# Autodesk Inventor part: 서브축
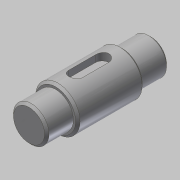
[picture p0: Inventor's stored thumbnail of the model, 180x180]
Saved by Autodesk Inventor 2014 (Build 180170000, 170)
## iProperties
Created: 2019-03
Part Number: 서브축
Material: 강철, 연강
Document SubType Name: Modeling
Designer: mduedu
Density: 1 g/cm^3
Appearance: 강철
Author: mduedu
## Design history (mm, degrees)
sketch "스케치1"
  geometry: L1 (0, 0)-(12, 0); L2 (12, 0)-(12, 8); L3 (12, 8)-(0, 8); L4 (0, 8)-(0, 0); L5 (12, 0)-(42, 0); L6 (42, 0)-(42, 10); L7 (42, 10)-(12, 10); L8 (12, 10)-(12, 0); L9 (42, 0)-(55, 0); L10 (55, 0)-(55, 8); L11 (55, 8)-(42, 8); L12 (42, 8)-(42, 0)
  constraints: 24 end point, 6 parallel, 3 horizontal, 3 perpendicular
  dimensions: "d0" = 16 diameter of L3 L1; "d2" = 20 diameter of L7 L5; "d3" = 16 diameter of L11 L9; "d4" = 12 distance of L2.end L3.end; "d5" = 30 distance of L6.end L7.end; "d6" = 55 distance between parallel lines of L10 L4
revolve "회전1" sketch "스케치1" stored, may be unused: angle "d7" = 90 deg
node "작업 평면1"
sketch "스케치2" dims "d10" = 18
  geometry: L1 (6, -3)-(-6, -3); L2 (-6, -3)-(-6, 3); L3 (-6, 3)-(6, 3); L4 (6, 3)-(6, -3); L5 (15, 10)-(15, -10) reference; 3 further points
  constraints: 8 end point, 2 midpoint, 2 parallel, 2 vertical alignment, 1 horizontal, 1 horizontal alignment, 1 perpendicular, 4 other
  dimensions: "d8" = 6 distance between parallel lines of L3 L1; "d11" = 6 dimension on L5
extrude "돌출1" cut sketch "스케치2" distance "d12" = 3.5; taper "d13" = 0 deg
chamfer "모따기1" distance "d14" = 1; stored, may be unused: second distance "d15" = 2, angle "d16" = 45 deg
chamfer "모따기2" distance "d17" = 1; stored, may be unused: second distance "d18" = 2, angle "d19" = 45 deg
node "솔리드1"
